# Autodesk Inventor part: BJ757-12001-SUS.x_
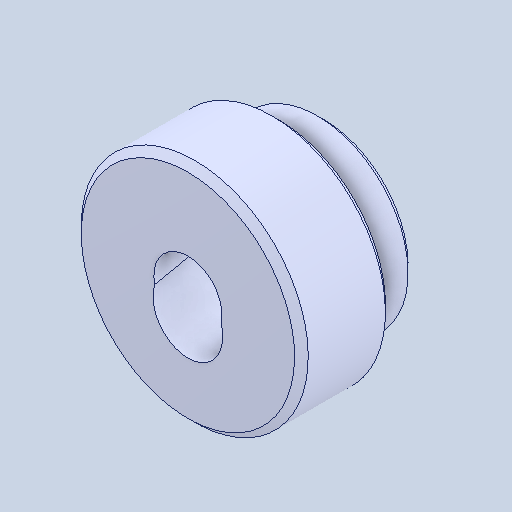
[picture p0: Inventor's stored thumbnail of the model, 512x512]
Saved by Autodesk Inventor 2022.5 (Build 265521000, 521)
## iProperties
Created: 2024-05
Part Number: BJ757-12001-SUS.x_
Material: 一般
Document SubType Name: Modeling
Designer: ImaoCorp
Density: 1 g/cm^3
Appearance: 既定
Author: ImaoCorp
Sending System: SOLIDWORKS 2022-2022290
MC: AMD64
MC_MODEL: Intel64 Family 6 Model 60 Stepping 3, GenuineIntel
OS: Windows_NT
FRU: Parasolid Version 33.1, build 260,  4-25-2022
FORMAT: text
GUISE: transmit
KEY: FILEBJ757-12001-SUS.x_t
DATE: Tue May 21 08:47:05 2024
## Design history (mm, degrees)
feature "Base1"
node "ソリッド1"
